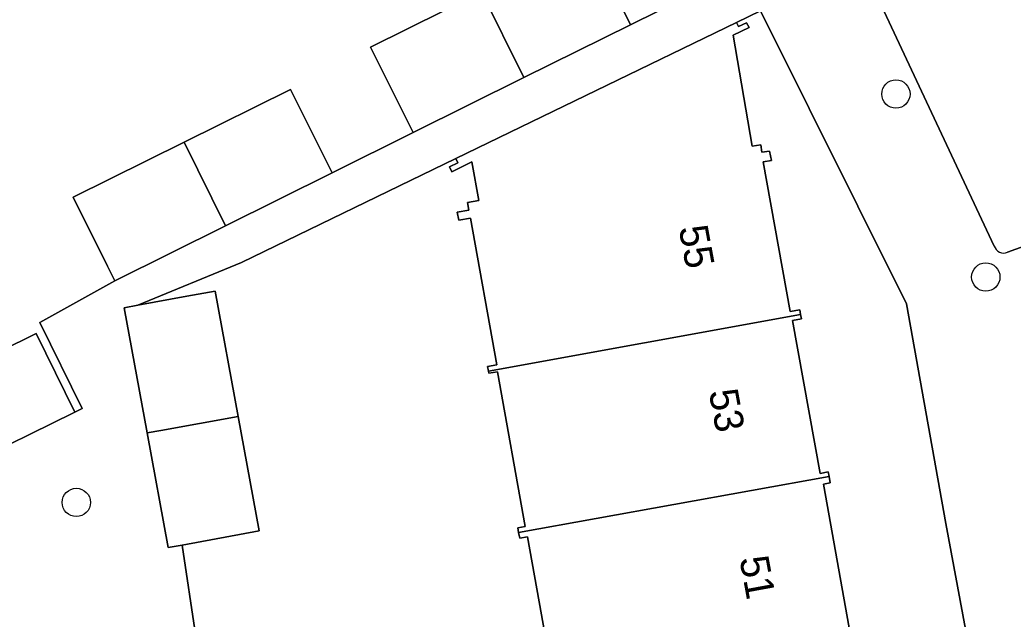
# Model space of a CAD drawing. Extents: x 157793 to 159380, y 380877 to 382313.
# Drawn here: x 158297.85 to 158332.13, y 381426.55 to 381447.24 of the extents above; entities that cross this region are included whole.
import ezdxf

# ---------------------------------------------------------------- set-up
doc = ezdxf.new("R2010")
doc.units = 0
for name, color, linetype in [('IMGEO_Boom', 7, 'Continuous'), ('IMGEO_Erf', 7, 'Continuous'), ('IMGEO_Pand', 7, 'Continuous'), ('IMGEO_Pand_nummerreeks', 7, 'Continuous'), ('IMGEO_Parkeervlak_open', 7, 'Continuous'), ('IMGEO_Voetpad_open', 7, 'Continuous')]:
    doc.layers.add(name, color=color, linetype=linetype)

msp = doc.modelspace()

# ---------------------------------------------------------------- linework, layer by layer
at = {"layer": 'IMGEO_Boom'}
for centre in [(158328.085, 381444.681), (158331.188, 381438.363), (158299.8, 381430.581)]:
    msp.add_circle(centre, 0.489, dxfattribs=at)
at = {"layer": 'IMGEO_Erf'}
for points in [[(158294.659, 381434.559), (158298.412, 381436.409), (158299.747, 381433.7), (158300.006, 381433.828), (158298.544, 381436.794), (158301.131, 381438.229), (158300.877, 381438.74), (158299.696, 381441.116), (158303.519, 381443.016), (158307.192, 381444.842), (158308.281, 381442.652), (158308.627, 381441.956), (158311.428, 381443.349), (158309.959, 381446.304), (158313.781, 381448.204), (158317.455, 381450.03), (158318.544, 381447.84), (158318.924, 381447.075), (158322.717, 381448.96), (158322.317, 381449.765), (158311.062, 381472.396), (158255.837, 381444.973)], [(158331.077, 381423.054), (158329.812, 381429.85), (158328.448, 381437.436), (158323.416, 381447.554), (158322.584, 381447.151), (158322.657, 381447.012), (158322.933, 381447.145), (158323.019, 381446.981), (158322.469, 381446.715), (158323.13, 381442.884), (158323.422, 381442.931), (158323.464, 381442.671), (158323.729, 381442.714), (158323.787, 381442.389), (158323.504, 381442.339), (158324.431, 381437.172), (158324.765, 381437.232), (158324.794, 381437.072), (158324.822, 381436.916), (158324.52, 381436.862), (158325.468, 381431.582), (158325.749, 381431.633), (158325.777, 381431.476), (158325.817, 381431.255), (158325.584, 381431.213), (158326.532, 381425.928)], [(158316.314, 381424.137), (158315.371, 381429.393), (158315.102, 381429.345), (158315.066, 381429.542), (158315.037, 381429.704), (158315.295, 381429.751), (158314.335, 381435.096), (158314.036, 381435.042), (158314.022, 381435.118), (158313.994, 381435.274), (158314.315, 381435.332), (158313.406, 381440.399), (158312.998, 381440.326), (158312.949, 381440.6), (158313.347, 381440.672), (158313.301, 381440.932), (158313.695, 381441.003), (158313.455, 381442.337), (158312.76, 381442), (158312.677, 381442.171), (158312.965, 381442.31), (158312.895, 381442.454), (158305.496, 381438.867), (158301.923, 381437.387), (158303.62, 381437.7), (158304.587, 381437.878), (158305.385, 381433.551), (158306.113, 381429.603), (158303.449, 381429.112), (158303.927, 381425.948)]]:
    msp.add_lwpolyline(points, dxfattribs=at)
at = {"layer": 'IMGEO_Pand'}
for points in [[(158313.781, 381448.204), (158315.25, 381445.249), (158318.924, 381447.075), (158318.544, 381447.84), (158317.455, 381450.03)], [(158313.781, 381448.204), (158309.959, 381446.304), (158311.428, 381443.349), (158315.25, 381445.249)], [(158323.504, 381442.339), (158323.787, 381442.389), (158323.729, 381442.714), (158323.464, 381442.671), (158323.422, 381442.931), (158323.13, 381442.884), (158322.469, 381446.715), (158323.019, 381446.981), (158322.933, 381447.145), (158322.657, 381447.012), (158322.584, 381447.151), (158312.895, 381442.454), (158312.965, 381442.31), (158312.677, 381442.171), (158312.76, 381442), (158313.455, 381442.337), (158313.695, 381441.003), (158313.301, 381440.932), (158313.347, 381440.672), (158312.949, 381440.6), (158312.998, 381440.326), (158313.406, 381440.399), (158314.315, 381435.332), (158313.994, 381435.274), (158314.022, 381435.118), (158324.794, 381437.072), (158324.765, 381437.232), (158324.431, 381437.172)], [(158304.954, 381440.13), (158308.627, 381441.956), (158308.281, 381442.652), (158307.192, 381444.842), (158303.519, 381443.016)], [(158304.954, 381440.13), (158303.519, 381443.016), (158299.696, 381441.116), (158300.877, 381438.74), (158301.131, 381438.229)], [(158304.587, 381437.878), (158303.62, 381437.7), (158301.923, 381437.387), (158301.447, 381437.299), (158302.243, 381432.981), (158302.72, 381433.068), (158305.385, 381433.551)], [(158324.52, 381436.862), (158324.822, 381436.916), (158324.794, 381437.072), (158314.022, 381435.118), (158314.036, 381435.042), (158314.335, 381435.096), (158315.295, 381429.751), (158315.037, 381429.704), (158315.066, 381429.542), (158325.777, 381431.476), (158325.749, 381431.633), (158325.468, 381431.582)], [(158294.659, 381434.559), (158296.003, 381431.854), (158299.704, 381433.679), (158299.747, 381433.7), (158298.412, 381436.409)], [(158305.385, 381433.551), (158302.72, 381433.068), (158302.243, 381432.981), (158302.973, 381429.024), (158303.449, 381429.112), (158306.113, 381429.603)], [(158316.077, 381423.959), (158326.887, 381425.827), (158326.859, 381425.987), (158326.532, 381425.928), (158325.584, 381431.213), (158325.817, 381431.255), (158325.777, 381431.476), (158315.066, 381429.542), (158315.102, 381429.345), (158315.371, 381429.393), (158316.314, 381424.137), (158316.054, 381424.09)]]:
    msp.add_lwpolyline(points, close=True, dxfattribs=at)
at = {"layer": 'IMGEO_Parkeervlak_open'}
for points in [[(158326.38, 381450.312), (158331.478, 381439.434)], [(158331.939, 381439.221), (158333.536, 381439.802), (158335.181, 381440.27)]]:
    msp.add_lwpolyline(points, dxfattribs=at)
msp.add_arc((158331.804, 381439.535), 0.342, 197.2309, 293.1715, dxfattribs=at)
at = {"layer": 'IMGEO_Voetpad_open'}
for points in [[(158326.38, 381450.312), (158325.692, 381451.847), (158323.708, 381450.89), (158316.546, 381465.245), (158316.267, 381466.353), (158312.782, 381473.207), (158311.062, 381472.396), (158322.317, 381449.765), (158322.717, 381448.96), (158323.394, 381447.598), (158323.416, 381447.554), (158328.448, 381437.436), (158329.812, 381429.85), (158331.077, 381423.054), (158333.81, 381407.731), (158335.126, 381400.425), (158338.102, 381383.483), (158338.683, 381380.173), (158341.696, 381380.704)], [(158331.478, 381439.434), (158326.38, 381450.312)], [(158303.927, 381425.948), (158303.449, 381429.112), (158302.973, 381429.024), (158302.243, 381432.981), (158301.447, 381437.299), (158301.923, 381437.387), (158305.496, 381438.867), (158312.895, 381442.454), (158322.584, 381447.151), (158323.416, 381447.554), (158323.394, 381447.598), (158322.717, 381448.96), (158318.924, 381447.075), (158315.25, 381445.249), (158311.428, 381443.349), (158308.627, 381441.956), (158304.954, 381440.13), (158301.131, 381438.229), (158298.544, 381436.794), (158300.006, 381433.828), (158299.747, 381433.7), (158299.704, 381433.679), (158296.003, 381431.854)], [(158335.181, 381440.27), (158333.536, 381439.802), (158331.939, 381439.221)]]:
    msp.add_lwpolyline(points, dxfattribs=at)
msp.add_arc((158331.804, 381439.535), 0.342, 197.2309, 293.1715, dxfattribs=at)

# ---------------------------------------------------------------- texts
at = {"layer": 'IMGEO_Pand_nummerreeks'}
for s, rotation, p in [('55', 280.4104, (158320.588, 381440.062)), ('53', 280.4104, (158321.626, 381434.41)), ('51', 280.4109, (158322.684, 381428.647))]:
    msp.add_text(s, height=1, rotation=rotation, dxfattribs=at).set_placement(p)

doc.saveas('drawing.dxf')
